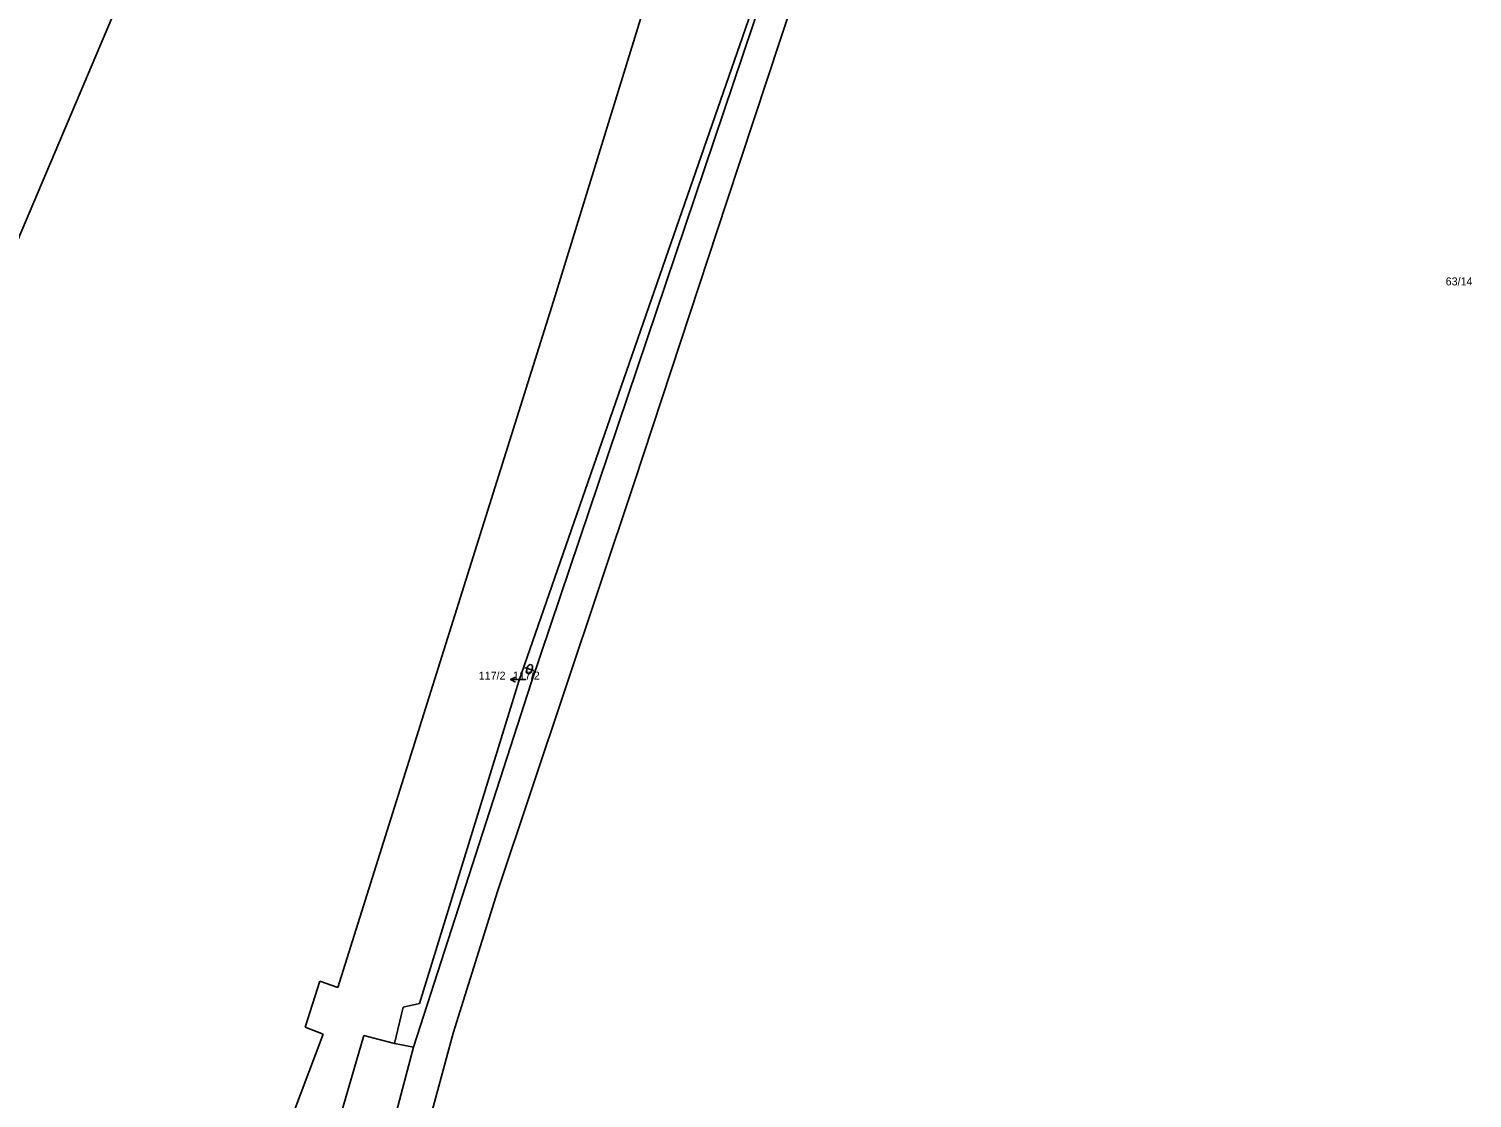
# Model space of a CAD drawing. Extents: x -752500 to -750336, y -1035826 to -1033500.
# Drawn here: x -752034.8 to -751728.2, y -1035246.4 to -1035019.2 of the extents above; entities that cross this region are included whole.
import ezdxf

# ---------------------------------------------------------------- set-up
doc = ezdxf.new("R2010")
doc.units = 0
for name, color, linetype in [('Default', 7, 'Continuous'), ('Hranice kat_území', 7, 'Continuous'), ('Hranice parcel', 7, 'Continuous'), ('Parcelní čísla', 7, 'Continuous'), ('Pop  PČ popisy', 7, 'Continuous'), ('Značky kultur', 7, 'Continuous')]:
    doc.layers.add(name, color=color, linetype=linetype)

# ---------------------------------------------------------------- blocks, each defined once
blk = doc.blocks.new('316')
at = {"layer": 'Default'}
for points in [[(-1, 1), (0.27, 1), (1, 1)], [(-0.5, 1.5), (-0.4, 1.79), (-0.15, 1.97), (0.16, 1.97), (0.41, 1.79), (0.51, 1.5), (0.51, 0.5), (0.41, 0.21), (0.16, 0.03), (-0.15, 0.03), (-0.4, 0.21), (-0.5, 0.5), (-0.5, 1.5)]]:
    blk.add_lwpolyline(points, dxfattribs=at)
blk = doc.blocks.new('10292')
at = {"layer": 'Default'}
blk.add_line((0, 3), (0, 0), dxfattribs=at)
blk.add_lwpolyline([(-0.5, 2), (0, 3), (0.5, 2)], dxfattribs=at)

msp = doc.modelspace()

# ---------------------------------------------------------------- linework, layer by layer
at = {"layer": 'Hranice kat_území'}
msp.add_line((-751999.82, -1034975.71), (-752067.65, -1035135.89), dxfattribs=at)
at = {"layer": 'Hranice parcel'}
for p, q in [((-751874.3, -1034995.18), (-751930.72, -1035157.76)), ((-751873.3, -1034995.38), (-751928.14, -1035158.13)), ((-751867.76, -1034999.09), (-751886.57, -1035055.86)), ((-751903.46, -1035012.4), (-751923.41, -1035077.01)), ((-751886.57, -1035055.86), (-751906.24, -1035115.63)), ((-751923.41, -1035077.01), (-751969.21, -1035222.9)), ((-751906.24, -1035115.63), (-751935.26, -1035202.5)), ((-751928.14, -1035158.13), (-751953.14, -1035235.55)), ((-751930.72, -1035157.76), (-751951.84, -1035226.26)), ((-751935.26, -1035202.5), (-751944.7, -1035232.59)), ((-751973.04, -1035221.51), (-751976.18, -1035231.31)), ((-751969.21, -1035222.9), (-751973.04, -1035221.51)), ((-751951.84, -1035226.26), (-751955.3, -1035227.07)), ((-751955.3, -1035227.07), (-751957.13, -1035234.8)), ((-751976.18, -1035231.31), (-751972.29, -1035232.78)), ((-751944.7, -1035232.59), (-751958.36, -1035282.73)), ((-751972.29, -1035232.78), (-752019.52, -1035357.91)), ((-751963.67, -1035233.09), (-752001.66, -1035362.46)), ((-751987.07, -1035365.19), (-751953.14, -1035235.55)), ((-751957.13, -1035234.8), (-751963.67, -1035233.09)), ((-751957.13, -1035234.8), (-751953.14, -1035235.55))]:
    msp.add_line(p, q, dxfattribs=at)
at = {"layer": 'Pop  PČ popisy'}
msp.add_line((-751929.23, -1035157.47), (-751929.49, -1035157.47), dxfattribs=at)

# ---------------------------------------------------------------- block references
at = {"layer": 'Pop  PČ popisy', "rotation": 90.01166999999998}
msp.add_blockref('10292', (-751929.49, -1035157.47), dxfattribs=at)
at = {"layer": 'Značky kultur', "rotation": -16.110730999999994}
msp.add_blockref('316', (-751928.77, -1035156.2), dxfattribs=at)

# ---------------------------------------------------------------- texts
at = {"layer": 'Parcelní čísla'}
for s, p in [('63/14', (-751733.83, -1035073.69)), ('117/2', (-751939.27, -1035157.47)), ('117/2', (-751932, -1035157.47))]:
    msp.add_text(s, height=1.7, dxfattribs=at).set_placement(p)

doc.saveas('drawing.dxf')
